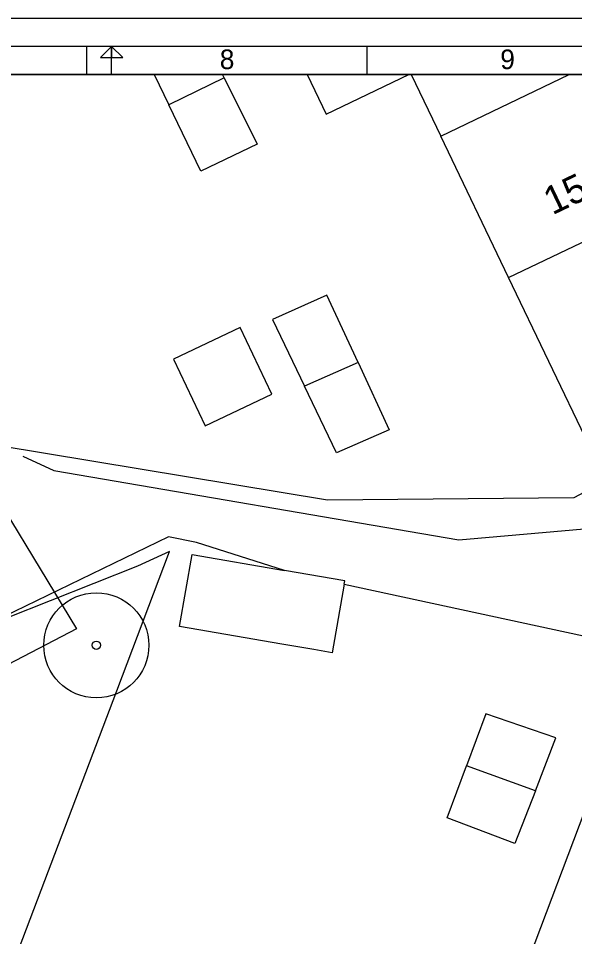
# Model space of a CAD drawing. Extents: x 192672 to 192910, y 446344 to 446512.
# Drawn here: x 192738.22 to 192758.05, y 446479 to 446511.76 of the extents above; entities that cross this region are included whole.
import ezdxf

# ---------------------------------------------------------------- set-up
doc = ezdxf.new("R2010")
doc.units = 0
for name, color, linetype in [('( Toegevoegd 29-11-2021 14_41_42) wegdeel vlak', 7, 'Continuous'), ('1010 viewport', 7, 'Continuous'), ('B-GV-GR-BOOM-S', 7, 'Continuous'), ('B-GV-KG-GRENS_WERKGRENS-G', 7, 'Continuous'), ('B-OI-KL-ET_LS-G', 7, 'Continuous'), ('grens maaiveld', 7, 'Continuous'), ('huisnummerreeks BGT', 7, 'Continuous'), ('pand op maaiveld vlak', 7, 'Continuous'), ('X-XX-AL-TEKENBLAD-S', 7, 'Continuous')]:
    doc.layers.add(name, color=color, linetype=linetype)

msp = doc.modelspace()

# ---------------------------------------------------------------- linework, layer by layer
at = {"layer": '( Toegevoegd 29-11-2021 14_41_42) wegdeel vlak'}
msp.add_line((192749.833, 446491.572), (192760.593, 446489.25), dxfattribs=at)
for points in [[(192765.561, 446498.667), (192758.023, 446494.654), (192749.243, 446494.562), (192737.517, 446496.509), (192736.353, 446498.833), (192734.578, 446497.242), (192732.701, 446497.637), (192731.791, 446499.455)], [(192747.709, 446492.058), (192744.573, 446493.06), (192743.573, 446493.255), (192737.693, 446490.405)]]:
    msp.add_lwpolyline(points, dxfattribs=at)
at = {"layer": '1010 viewport'}
msp.add_lwpolyline([(192675.743, 446509.756), (192860.643, 446509.756), (192860.643, 446345.556), (192675.743, 446345.556)], close=True, dxfattribs=at)
at = {"layer": 'B-GV-GR-BOOM-S'}
for radius in [1.875, 0.15]:
    msp.add_circle((192740.997, 446489.39), radius, dxfattribs=at)
at = {"layer": 'B-GV-KG-GRENS_WERKGRENS-G'}
msp.add_lwpolyline([(192740.295, 446489.973), (192734.557, 446486.987), (192730.473, 446485.129), (192725.366, 446482.882), (192721.029, 446481.333), (192717.923, 446480.635), (192713.732, 446480.061), (192710.196, 446479.993), (192707.335, 446480.383), (192700.156, 446483.797), (192705.941, 446486.582), (192708.78, 446485.232), (192710.487, 446485), (192713.343, 446485.054), (192717.034, 446485.56), (192719.635, 446486.145), (192723.516, 446487.53), (192728.43, 446489.693), (192732.367, 446491.484), (192737.694, 446494.256)], close=True, dxfattribs=at)
at = {"layer": 'B-OI-KL-ET_LS-G'}
msp.add_lwpolyline([(192738.378, 446496.142), (192739.482, 446495.624), (192753.92, 446493.148), (192759.346, 446493.622), (192761.266, 446495.244), (192761.834, 446495.904)], dxfattribs=at)
at = {"layer": 'grens maaiveld'}
for p, q in [((192739.028, 446480.658), (192741.724, 446487.765)), ((192734.733, 446469.332), (192739.028, 446480.658))]:
    msp.add_line(p, q, dxfattribs=at)
msp.add_lwpolyline([(192741.724, 446487.765), (192743.611, 446492.741), (192742.468, 446492.211), (192737.789, 446490.36), (192737.693, 446490.405)], dxfattribs=at)
at = {"layer": 'pand op maaiveld vlak'}
for p, q in [((192743.058, 446509.756), (192743.579, 446508.676)), ((192745.557, 446509.631), (192743.579, 446508.676)), ((192745.557, 446509.631), (192745.495, 446509.756)), ((192752.22, 446509.756), (192753.275, 446507.558)), ((192753.275, 446507.558), (192757.855, 446509.756)), ((192755.698, 446502.509), (192753.275, 446507.558)), ((192755.698, 446502.509), (192762.189, 446505.624)), ((192750.328, 446499.483), (192748.417, 446498.632)), ((192756.65, 446484.203), (192754.199, 446485.088)), ((192758.419, 446483.499), (192756.316, 446477.935))]:
    msp.add_line(p, q, dxfattribs=at)
for points in [[(192745.557, 446509.631), (192746.733, 446507.266), (192744.722, 446506.306), (192743.579, 446508.676)], [(192748.511, 446509.756), (192749.19, 446508.34), (192752.14, 446509.756)], [(192765.063, 446499.636), (192758.571, 446496.521), (192755.698, 446502.509)], [(192750.328, 446499.483), (192749.221, 446501.884), (192747.277, 446501.007), (192748.417, 446498.632)], [(192743.745, 446499.601), (192744.873, 446497.221), (192747.254, 446498.35), (192746.127, 446500.729), (192743.745, 446499.601)], [(192750.328, 446499.483), (192751.436, 446497.081), (192749.558, 446496.256), (192748.417, 446498.632)], [(192749.833, 446491.572), (192749.408, 446489.125), (192748.749, 446489.239), (192747.607, 446489.431), (192743.964, 446490.063), (192744.41, 446492.631), (192747.709, 446492.058)], [(192749.833, 446491.572), (192749.853, 446491.686), (192747.709, 446492.058)], [(192756.65, 446484.203), (192757.379, 446486.084), (192754.888, 446486.941), (192754.199, 446485.088)], [(192756.65, 446484.203), (192755.92, 446482.321), (192753.509, 446483.234), (192754.199, 446485.088)]]:
    msp.add_lwpolyline(points, dxfattribs=at)
at = {"layer": 'X-XX-AL-TEKENBLAD-S'}
for p, q in [((192909.543, 446511.756), (192671.743, 446511.756)), ((192908.543, 446510.756), (192674.743, 446510.756)), ((192740.643, 446510.756), (192740.643, 446509.756)), ((192741.543, 446509.756), (192741.543, 446510.756)), ((192750.643, 446510.756), (192750.643, 446509.756))]:
    msp.add_line(p, q, dxfattribs=at)
for points in [[(192741.543, 446510.356), (192741.543, 446510.756), (192741.143, 446510.356), (192741.543, 446510.356)], [(192741.543, 446510.756), (192741.543, 446510.356), (192741.943, 446510.356), (192741.543, 446510.756)]]:
    msp.add_lwpolyline(points, dxfattribs=at)
msp.add_lwpolyline([(192675.743, 446345.556), (192907.543, 446345.556), (192907.543, 446509.756), (192675.743, 446509.756)], close=True, dxfattribs=at)

# ---------------------------------------------------------------- texts
at = {"layer": 'huisnummerreeks BGT'}
msp.add_text('153', height=1, rotation=25.6, dxfattribs=at).set_placement((192757.254, 446504.724))
at = {"layer": 'X-XX-AL-TEKENBLAD-S'}
for s, p in [('8', (192745.399, 446509.945)), ('9', (192755.399, 446509.945))]:
    msp.add_text(s, height=0.7, dxfattribs=at).set_placement(p)

doc.saveas('drawing.dxf')
